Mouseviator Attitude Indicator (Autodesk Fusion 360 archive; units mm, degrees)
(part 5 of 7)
sketch "Sketch2"
  dimension "d14_1" = 20.32 (= "dip16_socket_length_1")
  dimension "d15_1" = 10.04 (= "dip16_socket_width_1")
extrude "Extrude2" sketch "Sketch2" blind 4.79 (= "dip16_socket_height_1 - dip16_socket_above_board_1") named "d16_1" taper 1 named "d17_1"
fillet "Fillet1" radius 0.5 named "d18_1"
sketch "Sketch3"
  dimension "d20_1" = 4
  dimension "d21_1" = 0.33
  dimension "d22_1" = 2.54
  dimension "d23_1" = 1.7
  dimension "d24_1" = 3.54 (= "0.1 in + 1 mm")
extrude "Extrude3" sketch "Sketch3" blind 1.5 named "d25_1"
extrude "Extrude4" sketch "Sketch3" blind 5.04 (= "dip16_socket_height_1") named "d27_1"
sketch "Sketch4"
  dimension "d29_1" = 9.04 (= "dip16_socket_width_1 - 1 mm")
  dimension "d30_1" = 1
  dimension "d31_1" = 5.04 (= "dip16_socket_height_1")
extrude "Extrude5" sketch "Sketch4" no distance stored
work_plane "WorkPlane1"
sketch "Sketch5"
  dimension "d33_1" = 5.04 (= "dip16_socket_height_1")
  dimension "d34_1" = 0.5
  dimension "d35_1" = 2.25
  dimension "d36_1" = 4.645 (= "( dip16_socket_width_1 - 0.75 mm ) / 2")
  dimension "d37_1" = 4.395 (= "( dip16_socket_width_1 - 1.25 mm ) / 2")
  dimension "d38_1" = 0.75 (= "dip16_socket_above_board_1 + 0.5 mm")
  dimension "d39_1" = 45
  dimension "d40_1" = 45
  dimension "d41_1" = 0.16 (= "dip16_socket_lead_thick_1")
  dimension "d42_1" = 0.25 (= "dip16_socket_above_board_1")
  dimension "d44_1" = 3
extrude "Extrude6" sketch "Sketch5" blind 1.25 (= "dip16_socket_lead_width_1") named "d45_1"
rectangular_pattern "R-Pattern1" countU 8 (= "dip16_num_leads_1 / 2") named "d50_1" uSpaceDistance -2.54 named "d52_1" vSpaceDistance 0 named "d53_1"
mirror "Mirror1"
work_plane "WorkPlane1" AlongDistance 8.89 (= "( ( dip16_num_leads_1 / 2 - 1 ) * dip16_socket_lead_spacing_1 ) / 2") named "d55_1"
sketch "Sketch1"
  dimension "d56_1" = 4.54 (= "dip16_socket_height_1 - 0.5 mm")
  dimension "d57_1" = 4.62 (= "dip16_socket_width_1 / 2 - 0.4 mm")
  dimension "d58_1" = 1.75
  dimension "d59_1" = 0.25
  dimension "d61_1" = 2.6667
  dimension "d62_1" = 0.76 (= "dip16_socket_above_board_1 + 0.51 mm")
  dimension "d63_1" = 0.5
  dimension "d64_1" = 0.67
  dimension "d65_1" = 97
  dimension "d66_1" = 1
  dimension "d67_1" = 0.5
  dimension "d68_1" = 0.16
  dimension "d71_1" = 0.16 (= "dip16_socket_lead_thick_1")
  dimension "d72_1" = 0.725
  dimension "d73_1" = 0.25
  dimension "d74_1" = 3.16 (= "dip16_socket_lead_length_1 - dip16_socket_height_1")
extrude "Extrude1" sketch "Sketch1" blind 0.625 (= "dip16_socket_lead_width_1 / 2") named "d69_1"
extrude "Extrude2" sketch "Sketch1" blind 0.31 (= "dip16_socket_lead_foot_width_1 / 2") named "d75_1"
sketch "Sketch2"
  dimension "d85_1" = 60
extrude "Extrude3" sketch "Sketch2" no distance stored
rectangular_pattern "R-Pattern1" countU 8 (= "dip16_num_leads_1 / 2") named "d77_1" uSpaceDistance -2.54 (= "-dip16_socket_lead_spacing_1") named "d79_1" vSpaceDistance 0 named "d80_1"
mirror "Mirror1"
sketch "Sketch1"
  circle C1 centre (10.16, 0) radius 0.625
  dimension "d82_1" diameter C1 = 1.25
  dimension "d83_1" distance = 10.16 (= "dip16_socket_length_1 / 2")
extrude "Extrude7" sketch "Sketch1" no distance stored
position "Position4"
work_plane "WorkPlane4" AlongDistance 2.5
sketch "Sketch3"
  dimension "d119" = 6
  dimension "d120" = 10
  dimension "d121" = 0.1
  dimension "d122" = 0.2
  dimension "d124" = 0.2
  dimension "d125" = 0.4
  dimension "d126" = 1.6
  dimension "d128" = 0.9
  dimension "d129" = 0.7
  dimension "d131" = 0.25
  dimension "d132" = 0.7
  dimension "d134" = 0.3
  dimension "d135" = 0.3
revolve "Revolve1" sketch "Sketch3" AlongAngle 360
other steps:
create_component "CreateComponent1"
create_component "CreateComponent4"
create_component "CreateComponent6"
create_component "CreateComponent7"
create_component "CreateComponent10"
create_component "CreateComponent1"
create_component "CreateComponent2"
create_component "CreateComponent11"
create_component "CreateComponent1"
create_component "CreateComponent1"
create_component "CreateComponent2"
create_component "CreateComponent3"
remove_instance "RemoveInstance1"
remove_instance "RemoveInstance2"
create_component "CreateComponent13"
create_component "CreateComponent1"
create_component "CreateComponent2"
create_component "CreateComponent3"
remove_instance "RemoveInstance1"
remove_instance "RemoveInstance2"
create_component "CreateComponent14"
create_component "CreateComponent1"
create_component "CreateComponent2"
create_component "CreateComponent15"

design "microswitch 10T85"
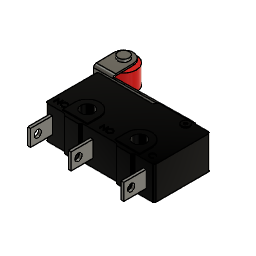
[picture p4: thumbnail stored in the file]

design "Bezel BOXY LED and Glass MS33638C" references "LED D5 - White-Clear"
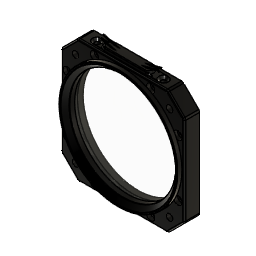
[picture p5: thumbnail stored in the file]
parameter "d52" = 0.15
canvas "Canvas4"
canvas "Canvas1"
canvas "Canvas5"
sketch "Instrument Sketch" plane through (0, 0, 0) normal (0, 1, 0) x axis (-1, 0, 0)
  line L1 (0, 0) -> (0, 39.6875)
  line L2 (-42.3978, 0) -> (0, 0)
  line L3 (-1.0967, 0) -> (0, 0)
  line L4 (-72.2485, 72.2485) -> (0, 0)
  line L5 (30, 41.2776) -> (0, 41.2776)
  line L6 (41.2776, 30) -> (30, 41.2776)
  line L7 (41.2776, 0) -> (41.2776, 30)
  line L8 (30, -41.2776) -> (0, -41.2776)
  line L9 (41.2776, -30) -> (30, -41.2776)
  line L10 (41.2776, 0) -> (41.2776, -30)
  line L11 (-30, 41.2776) -> (0, 41.2776)
  line L12 (-41.2776, 30) -> (-30, 41.2776)
  line L13 (-41.2776, 0) -> (-41.2776, 30)
  line L14 (-30, -41.2776) -> (0, -41.2776)
  line L15 (-41.2776, -30) -> (-30, -41.2776)
  line L16 (-41.2776, 0) -> (-41.2776, -30)
  circle C1 centre (0, 0) radius 39.6875
  circle C2 centre (31.4309, 31.4309) radius 2.159
  circle C3 centre (-31.4309, -31.4309) radius 2.159
  circle C4 centre (-31.4309, 31.4309) radius 2.159
  circle C5 centre (31.4309, -31.4309) radius 2.159
  circle C6 centre (0, 0) radius 35.5256
  point P1 (0, 0)
  point P2 (0, 0)
  point P11 (0, 0)
  point P13 (0, 0)
  point P14 (-1.0967, 0)
  point P12 (0, 0)
  point P15 (0, 0)
  point P4 (0, 39.6875)
  point P18 (0, 41.2776)
  point P19 (0, 41.2776)
  point P9 (0, 0)
  point P22 (41.2776, 0)
  point P10 (0, 0)
  point P23 (0, -41.2776)
  point P20 (30, 41.2776)
  point P24 (30, -41.2776)
  point P21 (41.2776, 30)
  point P25 (41.2776, -30)
  point P26 (41.2776, 0)
  point P27 (0, 41.2776)
  point P28 (-30, 41.2776)
  point P29 (-41.2776, 30)
  point P30 (-41.2776, 0)
  point P31 (0, -41.2776)
  point P32 (-30, -41.2776)
  point P33 (-41.2776, -30)
  point P34 (-41.2776, 0)
  coincident P1 P2
  equal C3 C4
  equal C3 C5
  equal C2 C5
  coincident P1 P11
  coincident P1 P13
  coincident L2 P14
  perpendicular L1 L3
  coincident P12 P15
  coincident C1 P4
  vertical L1
  coincident P18 P19
  perpendicular L1 L5
  vertical L7
  horizontal P9 P22
  vertical P10 P18
  coincident P2 P12
  coincident P2 P9
  vertical P12 P18
  symmetric L2 P19 P23
  symmetric L2 P20 P24
  symmetric L2 P21 P25
  symmetric L2 P22 P26
  symmetric L1 P19 P27
  symmetric L1 P20 P28
  symmetric L1 P21 P29
  symmetric L1 P22 P30
  symmetric L1 P23 P31
  symmetric L1 P24 P32
  symmetric L1 P25 P33
  symmetric L1 P26 P34
  dimension "d1" diameter C1 = 79.375 (= "3 1/8")
  dimension "d13" angle L1 L4 = 45 (= "Angular Dimension-2")
  dimension "d150" angle L5 L6 = 135 (= "Angular Dimension-3")
  dimension "d151" distance P19 P20 = 30
  dimension "d152" distance P21 P22 = 30
extrude "Extrude1" new body sketch "Instrument Sketch" profile of C1 C2 C3 C4 C5 C6 along a picked direction blind 10.25
extrude "Extrude2" sketch "Instrument Sketch" profile of C1 C6 blind 3
chamfer "Chamfer1" distance 3
canvas "Canvas2"
canvas "Canvas3"
move "Move1"
fillet "Fillet1" radius 0.5 0.25
sketch "Sketch2" plane through (0, 0, 0) normal (0, 1, 0) x axis (-1, 0, 0)
  line L1 (0, 32.0284) -> (0, 40.649)
  line L2 (-1.5, -39.15) -> (1.5, -39.15)
  line L3 (-1.5, -41.65) -> (-1.5, -39.15)
  line L4 (1.5, -41.65) -> (-1.5, -41.65)
  line L5 (1.5, -39.15) -> (1.5, -41.65)
  line L6 (-1.5, -41.65) -> (1.5, -39.15)
  line L7 (1.5, -41.65) -> (-1.5, -39.15)
  line L8 (30, -41.2776) -> (-30, -41.2776)
  line L9 (41.2776, -30) -> (30, -41.2776)
  line L10 (41.2776, 30) -> (41.2776, -30)
  line L11 (30, 41.2776) -> (41.2776, 30)
  line L12 (-30, 41.2776) -> (30, 41.2776)
  line L13 (-41.2776, 30) -> (-30, 41.2776)
  line L14 (-41.2776, -30) -> (-41.2776, 30)
  line L15 (-30, -41.2776) -> (-41.2776, -30)
  circle C1 centre (-31.4309, -31.4309) radius 2.159
  circle C2 centre (31.4309, 31.4309) radius 2.159
  circle C3 centre (31.4309, -31.4309) radius 2.159
  circle C4 centre (-31.4309, 31.4309) radius 2.159
  circle C5 centre (0, 0) radius 35.5256
  circle C6 centre (0, 0) radius 39.65
  point P1 (0, 0)
  point P7 (0, 0)
  point P9 (0, 32.0284)
  point P10 (0, 35.3825)
  point P11 (0.742, 39.6431)
  point P16 (0, -40.4)
  point P14 (-1.5, -41.65)
  point P15 (1.5, -41.65)
  point P13 (-1.5, -39.15)
  coincident P1 P7
  vertical L1
  vertical P7 P9
  coincident L1 P10
  coincident C6 P11
  horizontal L2
  perpendicular L2 L3
  parallel L2 L4
  parallel L3 L5
  coincident L6 P16
  coincident L7 P16
  vertical P1 P16
  dimension "d19" diameter C6 = 79.3
  dimension "d50" distance P14 P15 = 3
  dimension "d51" distance P13 P14 = 2.5
  dimension "d67" distance C6 L4 = 2
extrude "Extrude3" cut sketch "Sketch2" profile of C5 C6 L2 L3 L4 L5 to an object offset -6.5
sketch "Sketch1" plane through (0, -6.75, 0) normal (0, 1, 0) x axis (-1, 0, 0)
  line L1 (0, 40.6) -> (0.6381, 39.4948)
  line L2 (-0.6381, 39.4948) -> (0, 40.6)
  line L3 (1.5, -39.6216) -> (1.5, -41.2776)
  line L4 (-1.5, -41.2776) -> (-1.5, -39.6216)
  line L5 (1.5, -41.2776) -> (-1.5, -41.2776)
  circle C1 centre (0, 0) radius 35.5256
  circle C2 centre (0, 0) radius 39.55
  arc A1 centre (0, 0) radius 39.5 clockwise from (0.6381, 39.4948) to (-0.6381, 39.4948)
  arc A2 centre (0, 0) radius 39.65 clockwise from (-1.5, -39.6216) to (1.5, -39.6216)
  point P1 (0, 0)
  point P3 (0, 0)
  coincident P1 P3
extrude "Extrude1" new body sketch "Sketch1" profile of C1 C2 L1 L2 A1 L3 L4 along normal blind 3
sketch "Sketch1" plane through (0, -3.75, 0) normal (0, 1, 0) x axis (-1, 0, 0)
  line L1 (1.35, -38.7521) -> (1.35, -39.6216)
  line L2 (-1.35, -38.2133) -> (-1.35, -39.6216)
  line L3 (1.35, -41.2776) -> (1.35, -39.6216)
  line L4 (1.5, -41.4276) -> (-1.5, -41.4276)
  line L5 (-1.35, -39.6216) -> (-1.35, -41.2776)
  line L6 (1.5, -39.6216) -> (1.5, -41.2776)
  line L7 (-1.5, -41.2776) -> (-1.5, -39.6216)
  line L8 (1.5, -41.2776) -> (-1.5, -41.2776)
  circle C1 centre (0, 0) radius 39.65
  circle C2 centre (0, 0) radius 36.65
  circle C3 centre (0, 0) radius 39.5
  parallel L1 L3
  parallel L2 L5
  dimension "d25" diameter C1 = 79.3
  dimension "d29" = -3
  dimension "d68" = -0.15
extrude "Extrude1" new body sketch "Sketch1" profile of C1 C2 L8 C3 L5 L3 L1 L2 to an object bodies "Seal"
sketch "Panel Sketch" plane through (0, -10.25, 0) normal (0, -1, 0) x axis (1, 0, 0)
  line L1 (30, -41.2776) -> (-30, -41.2776)
  line L2 (41.2776, -30) -> (30, -41.2776)
  line L3 (41.2776, 30) -> (41.2776, -30)
  line L4 (30, 41.2776) -> (41.2776, 30)
  line L5 (-30, 41.2776) -> (30, 41.2776)
  line L6 (-41.2776, 30) -> (-30, 41.2776)
  line L7 (-41.2776, -30) -> (-41.2776, 30)
  line L8 (-30, -41.2776) -> (-41.2776, -30)
  circle C1 centre (31.4309, 31.4309) radius 2.159
  circle C2 centre (-31.4309, -31.4309) radius 2.159
  circle C3 centre (-31.4309, 31.4309) radius 2.159
  circle C4 centre (31.4309, -31.4309) radius 2.159
  circle C5 centre (0, 0) radius 39.6875
sketch "Clamping Holes" plane through (0, -10.25, 0) normal (0, -1, 0) x axis (1, 0, 0)
  line L1 (0, 17.2297) -> (0, 0)
  line L2 (-22.2137, 0) -> (0, 0)
  circle C1 centre (-36.96, 18.76) radius 1
  circle C2 centre (36.96, 18.76) radius 1
  circle C3 centre (-36.96, -18.76) radius 1
  circle C4 centre (36.96, -18.76) radius 1
  circle C5 centre (-18.76, 36.96) radius 1
  circle C6 centre (18.76, 36.96) radius 1
  circle C7 centre (18.76, -36.96) radius 1
  circle C8 centre (-18.76, -36.96) radius 1
  point P1 (0, 0)
  point P3 (0, 0)
  point P5 (0, 0)
  point P2 (-36.96, 18.76)
  point P10 (-18.76, 36.96)
  coincident P1 P3
  vertical L1
  coincident P1 P5
  perpendicular L1 L2
  symmetric C1 L1 C2
  symmetric C1 L2 C3
  symmetric L2 C2 C4
  symmetric L1 C5 C6
  symmetric L2 C5 C8
  symmetric L2 C6 C7
  dimension "d32" diameter C1 = 2
  dimension "d33" distance P1 P2 = 18.76 (= "( 37.52 / 2 ) * 1 mm")
  dimension "d34" distance P1 P2 = 36.96 (= "( 73.92 / 2 ) * 1 mm")
  dimension "d37" diameter C5 = 2 (= "d32")
  dimension "d38" distance P1 P10 = 36.96 (= "d34")
  dimension "d39" distance P1 P10 = 18.76 (= "d33")
hole "Hole1" HoleDepth 10.25 HoleDiameter 2.8 CBDepth 2.5 CBDiameter 5.5
component_from_bodies "Body->Comp"
sketch "Top Sketch" plane through (0, 0, 41.4655) normal (0, 0, 1) x axis (-1, 0, 0)
  line L1 (-22.19, 8) -> (22.19, 8)
  line L2 (22.19, 2) -> (-22.19, 2)
  line L3 (-22.19, 5) -> (22.19, 5)
  line L4 (22.19, 1.85) -> (-22.19, 1.85)
  line L5 (-22.19, 8.15) -> (22.19, 8.15)
  line L6 (-15.15, 1.85) -> (15.15, 1.85)
  line L7 (-15.15, 8.15) -> (-15.15, 1.85)
  line L8 (15.15, 8.15) -> (-15.15, 8.15)
  line L9 (15.15, 1.85) -> (15.15, 8.15)
  line L10 (-15.15, 8.15) -> (15.15, 1.85)
  line L11 (15.15, 8.15) -> (-15.15, 1.85)
  line L12 (-30, 0) -> (30, 0)
  line L13 (30, 0) -> (-30, 0)
  line L14 (30, 10.25) -> (30, 0)
  line L15 (-30, 10.25) -> (30, 10.25)
  line L16 (-30, 0) -> (-30, 10.25)
  arc A1 centre (-22.19, 5) radius 3 clockwise from (-22.19, 2) to (-22.19, 8)
  arc A2 centre (22.19, 5) radius 3 clockwise from (22.19, 8) to (22.19, 2)
  arc A3 centre (22.19, 5) radius 3.15 clockwise from (22.19, 8.15) to (22.19, 1.85)
  arc A4 centre (-22.19, 5) radius 3.15 clockwise from (-22.19, 1.85) to (-22.19, 8.15)
  point P8 (0, 5)
  point P1 (0, 0)
  point P15 (15.15, 1.85)
  point P19 (0, 5)
  point P7 (-22.19, 5)
  point P6 (22.19, 5)
  point P17 (-15.15, 8.15)
  point P18 (15.15, 8.15)
  tangent L1 A1
  tangent A1 L2
  parallel L1 L2
  tangent L2 A2
  tangent L1 A2
  horizontal L3
  midpoint L3 P8
  vertical P1 P8
  horizontal L6
  perpendicular L6 L7
  parallel L6 L8
  parallel L7 L9
  coincident L4 P15
  coincident L10 P19
  coincident L11 P19
  coincident P8 P19
  dimension "d54" diameter A1 = 6
  dimension "d56" distance P7 L12 = 5
  dimension "d57" distance P6 P7 = 44.38
  dimension "d60" = 0.15
  dimension "d70" distance P17 P18 = 30.3
extrude "Extrude2" cut sketch "Top Sketch" profile of L1 A1 L2 A2 L4 L5 A3 A4 against normal blind 1.7
extrude "Extrude2" cut sketch "Top Sketch" profile of L1 L2 L4 L5 L6 L7 L8 L9 to an object
work_plane "WorkPlane1"
sketch "LED Angle" plane through (0, -5, 41.4655) normal (0, -1, 0) x axis (1, 0, 0)
  line L1 (14.8802, -5) -> (-0.0147, -1.0089)
  line L2 (50, -10.3752) -> (0, -10.3752)
  line L3 (0, 22.6624) -> (0, -10.6292)
  line L4 (-14.8802, -5) -> (-0.0147, -1.0089)
  line L5 (-30, -0.1879) -> (30, -0.1879)
  point P1 (0, 0)
  point P2 (0, -10.6292)
  point P3 (14.8802, -5)
  point P8 (-14.8802, -5)
  horizontal L2
  vertical P1 P2
  perpendicular L2 L3
  symmetric P3 L3 P8
  dimension "d104" angle L1 L2 = 15 (= "Angular Dimension-2")
pipe "Pipe2" SectionSize 6.5 SectionThickness 1.375
component_insert "Component Insert"
joint "Assemble1" alignOffsetX 0 alignOffsetY 0 alignOffsetZ -3
copy_paste "CutPaste"
work_plane "WorkPlane1"
mirror_component "MirrorComponent1"
derived_instance "DerivedInstance1"
mirror "Mirror1" mirrorStitchTolerance 0.1
extrude "Extrude1" new body sketch "Top Sketch" profile of L1 A1 L2 A2 L7 L9 against normal blind 1.7 bodies "Top LED Holder"
sketch "Top Sketch" plane through (0, 0, 41.4655) normal (0, 0, 1) x axis (-1, 0, 0)
  line L1 (-22.19, 8) -> (22.19, 8)
  line L2 (22.19, 2) -> (-22.19, 2)
  line L3 (0, 8) -> (0, 2)
  line L4 (-12.5, 7.975) -> (12.5, 7.975)
  line L5 (12.5, 2.025) -> (-12.5, 2.025)
  line L6 (-12.5, 5) -> (12.5, 5)
  line L7 (-13.6, 8.9) -> (13.6, 8.9)
  line L8 (13.6, 1.1) -> (-13.6, 1.1)
  line L9 (-13.6, 5) -> (13.6, 5)
  arc A1 centre (22.19, 5) radius 3 clockwise from (22.19, 8) to (22.19, 2)
  arc A2 centre (-22.19, 5) radius 3 clockwise from (-22.19, 2) to (-22.19, 8)
  arc A3 centre (-12.5, 5) radius 2.975 clockwise from (-12.5, 2.025) to (-12.5, 7.975)
  arc A4 centre (12.5, 5) radius 2.975 clockwise from (12.5, 7.975) to (12.5, 2.025)
  arc A5 centre (-13.6, 5) radius 3.9 clockwise from (-13.6, 1.1) to (-13.6, 8.9)
  arc A6 centre (13.6, 5) radius 3.9 clockwise from (13.6, 8.9) to (13.6, 1.1)
  circle C1 centre (-15.475, 5) radius 2.5
  circle C2 centre (15.475, 5) radius 2.5
  circle C3 centre (16.5801, 5) radius 1.5
  point P8 (0, 2)
  point P9 (0, 8)
  point P16 (0, 5)
  point P22 (-13.6, 5)
  point P23 (0, 5)
  point P24 (-15.475, 5)
  point P25 (15.475, 5)
  point P26 (16.5801, 5)
  midpoint L2 P8
  midpoint L1 P9
  tangent L4 A3
  tangent A3 L5
  parallel L4 L5
  tangent L5 A4
  tangent L4 A4
  perpendicular L3 L6
  midpoint L3 P16
  midpoint L6 P16
  tangent L7 A5
  tangent A5 L8
  parallel L7 L8
  tangent L8 A6
  tangent L7 A6
  coincident L6 P22
  parallel L6 L9
  coincident P16 P23
  midpoint L9 P23
  midpoint A3 P24
  midpoint A4 P25
  horizontal P23 P26
  dimension "d115" distance L4 L5 = 5.95
  dimension "d116" = 30.95
  dimension "d117" distance L7 L8 = 7.8
  dimension "d118" = 35
  dimension "d123" diameter C2 = 5
  dimension "d124" diameter C1 = 5 (= "d123")
  dimension "d126" diameter C3 = 3
extrude "Extrude2" add sketch "Top Sketch" profile of L4 A3 L5 A4 C1 C2 C3 along normal blind 2
extrude "Extrude3" add sketch "Top Sketch" profile of L1 L2 L4 A3 L5 A4 L7 A5 L8 A6 C1 C2 along normal blind 1
chamfer "Chamfer1" distance 0.8
extrude "Extrude4" cut sketch "Top Sketch" profile of A4 A6 C2 C3 to an object
sketch "Bottom Sketch" plane through (0, 0, 39.7655) normal (0, 0, -1) x axis (1, 0, 0)
  line L1 (22.19, 2) -> (-22.19, 2)
  line L2 (-22.19, 8) -> (22.19, 8)
  line L3 (9, 2) -> (-9, 2)
  line L4 (-9, 8) -> (9, 8)
  line L5 (9, 5) -> (-9, 5)
  line L6 (-11.5981, 6.5) -> (-16.5801, 6.5)
  line L7 (-11.5981, 3.5) -> (-11.5981, 6.5)
  line L8 (-16.5801, 3.5) -> (-11.5981, 3.5)
  line L9 (-16.5801, 6.5) -> (-16.5801, 3.5)
  circle C1 centre (-16.5801, 5) radius 1.5
  arc A1 centre (-22.19, 5) radius 3 clockwise from (-22.19, 2) to (-22.19, 8)
  arc A2 centre (22.19, 5) radius 3 clockwise from (22.19, 8) to (22.19, 2)
  circle C2 centre (-16.5801, 5) radius 1
  arc A3 centre (9, 5) radius 3 clockwise from (9, 8) to (9, 2)
  arc A4 centre (-9, 5) radius 3 clockwise from (-9, 2) to (-9, 8)
  point P16 (0, 5)
  point P19 (-11.5981, 3.5)
  point P17 (-16.5801, 6.5)
  point P20 (-16.5801, 3.5)
  point P9 (-16.5801, 5)
  point P1 (0, 0)
  point P15 (9, 5)
  concentric C1 C2
  tangent L3 A3
  tangent A3 L4
  parallel L3 L4
  tangent L4 A4
  tangent L3 A4
  parallel L1 L5
  midpoint L5 P16
  horizontal L6
  vertical L7
  horizontal L8
  vertical L9
  coincident A4 P19
  coincident C1 P17
  coincident C1 P20
  vertical P9 P20
  vertical P1 P16
  horizontal P9 P16
  dimension "d129" diameter A3 = 6
  dimension "d130" distance P15 P16 = 9
extrude "Extrude5" cut sketch "Bottom Sketch" profile of C1 L1 L2 L3 A3 L4 A4 L6 L7 L8 against normal blind 1
extrude "Extrude6" cut sketch "Bottom Sketch" profile of L1 L2 L3 A3 L4 A4 L7 against normal blind 2.5
work_plane "WorkPlane1"
hole "Hole1" HoleDepth 7 HoleDiameter 3.2 CSDiameter 6.3
fillet "Fillet1" radius 2 1
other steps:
derived_base_feature "Derived Base Feature"
pipe "Pipe2" SectionSize 6.5 SectionThickness 1.375
mirror "Mirror1" mirrorStitchTolerance 0.1
base_feature "Base Feature" bodies "Standard Bezel"
extrude "Extrude1" cut sketch "Top Sketch" profile of L1 A1 L2 A2 L4 L5 A3 A4 against normal blind 1.7
pipe "Pipe2" SectionSize 6.5 SectionThickness 1.375
mirror "Mirror1" mirrorStitchTolerance 0.1
hole "Hole1" HoleDepth 7 HoleDiameter 3.2 CSDiameter 6.3
create_component "CreateComponent1"
create_component "CreateComponent2"
create_component "CreateComponent4"
remove_body "RemoveBody1"
extrude "Extrude2" cut sketch "Top Sketch" profile of L1 A1 L2 A2 L4 L5 A3 A4 against normal blind 1.7
joint_origin "JointOrigin1"
create_component "CreateComponent5"
remove_instance "RemoveInstance1"
create_component "CreateComponent1"
create_component "CreateComponent6"
named bodies: "Standard Bezel", "Seal", "Top LED Holder"

design "LED D5 - White-Clear"
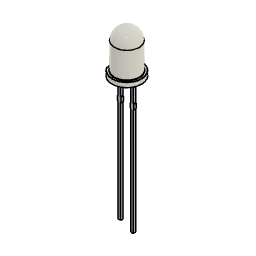
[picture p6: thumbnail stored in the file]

design "G1000/Steam C172 Panel Sketch"
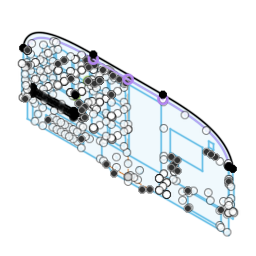
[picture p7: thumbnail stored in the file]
parameter "Instrumentknobdimension" = 6.35 (= "0.25")
parameter "d3" = 4.318 (= "0.17")
parameter "d241" = 37
parameter "d250" = 10
parameter "d252" = 10
parameter "d294" = 6.35 (= "0.25")
parameter "d300" = 2
parameter "d302" = 1
parameter "d146" = 4.318 (= "0.17")
parameter "d314" = 342.9 (= "13.5")
parameter "d247" = 6.35 (= "Instrumentknobdimension")
parameter "d248" = 6.35 (= "Instrumentknobdimension")
parameter "d329" = 8.001 (= "0.315")
parameter "d386" = 7.62 (= "0.3")
parameter "d104" = 270 (= "d101")
base_feature "Base Feature"
copy_paste "CutPaste"
canvas "Canvas1"
canvas "Canvas3"
canvas "Canvas6"
canvas "Canvas7"
canvas "Canvas9" sketch "Analog Master"
canvas "Canvas10" sketch "Analog Master"
sketch "Analog Master" plane through (0, 0, 0) normal (0, 1, 0) x axis (1, 0, 0)
  line L1 (-172.9706, -420) -> (0, -420)
  curve K1 (69.9424, 20) -> (107.8843, 0)
  curve K2 (104.8876, -0.1472) -> (110.8811, 0.1472)
  curve K3 (65.1162, 20) -> (74.7686, 20)
  line L2 (-351.7202, -281.627) -> (-346.953, -286.548)
  line L3 (-230, -95.25) -> (-230, -204.9762)
  line L4 (-81.0384, -309.4306) -> (-77.9862, -312.4827)
  line L5 (-132.2958, -407.803) -> (-200.571, -407.803)
  line L6 (-200.571, -387.483) -> (-132.2958, -387.483)
  line L7 (-141.0632, -344.0205) -> (-183.9378, -301.1803)
  line L8 (154.9321, -66.0556) -> (171.4865, -66.0556)
  line L9 (183.7415, -29.4869) -> (190.7415, -29.4869)
  line L10 (0, 20) -> (-69.9424, 20)
  line L11 (-125.1584, -397.643) -> (-207.7084, -397.643)
  line L12 (-350.0664, -224.1613) -> (-345.1455, -219.3941)
  line L13 (-215.012, -148.0279) -> (-244.9883, -193.745)
  line L14 (176.0865, -23.2779) -> (183.7415, -23.2779)
  line L15 (171.4865, -69.6959) -> (171.4865, -66.0556)
  line L16 (-387.2335, -62.0569) -> (-407.5535, -31.1959)
  line L17 (183.7415, -63.4869) -> (183.7415, -69.6959)
  line L18 (154.9321, -27.0556) -> (176.0865, -27.0556)
  line L19 (-194.9837, -314.302) -> (-199.7509, -309.3811)
  line L20 (183.7415, -23.2779) -> (183.7415, -29.4869)
  line L21 (-475.361, -115.57) -> (-270.51, -115.57)
  line L22 (154.9321, -27.0556) -> (154.9321, -66.0556)
  line L23 (-72.0304, -387.5197) -> (-14.8804, -407.8397)
  line L24 (-97.5147, -420) -> (-97.5147, -204.6151)
  curve K4 (-172.9706, -420) -> (-500, -294.703)
  curve K5 (-500, -302.074) -> (-500, -287.3319)
  curve K6 (-81.7028, -420) -> (-264.2385, -420)
  line L25 (-500, 0) -> (-500, -294.703)
  line L26 (-77.9862, -312.4827) -> (-82.4764, -316.9729)
  line L27 (-362.4853, -405.0994) -> (-362.4853, -205.3372)
  line L28 (-68.068, -387.5197) -> (-18.8428, -387.5197)
  line L29 (183.7415, -69.6959) -> (171.4865, -69.6959)
  line L30 (-11.7054, -397.6797) -> (-75.2054, -397.6797)
  line L31 (0, 20) -> (69.9424, 20)
  line L32 (-97.5147, -204.6151) -> (-362.4853, -205.3372)
  line L33 (430.0639, -313.9668) -> (394.0639, -291.2168)
  line L34 (303.15, -12.7) -> (455.55, -12.7)
  line L35 (230, -95.25) -> (230, -170.8864)
  line L36 (226.825, -136.7885) -> (226.825, -151.8364)
  line L37 (461.9, -19.05) -> (461.9, -82.55)
  line L38 (190.7415, -63.4869) -> (183.7415, -63.4869)
  line L39 (-215.0138, -193.7463) -> (-244.9862, -148.0266)
  line L40 (-350.9585, -313.9207) -> (-347.9064, -316.9729)
  line L41 (-221.945, -62.2703) -> (-242.265, -62.2703)
  line L42 (-129.4939, -406.6425) -> (-203.3728, -388.6436)
  line L43 (-343.4162, -312.4827) -> (-346.4684, -309.4306)
  line L44 (-262.7234, -316.3565) -> (-257.8025, -311.5893)
  line L45 (176.0865, -27.0556) -> (176.0865, -23.2779)
  line L46 (-82.4764, -316.9729) -> (-85.5285, -313.9207)
  line L47 (-407.5535, -62.0569) -> (-387.2335, -31.1959)
  line L48 (-284.4986, -279.1718) -> (-289.4196, -283.939)
  line L49 (-141.0006, -273.7447) -> (-141.0006, -252.9947)
  line L50 (-221.945, -62.2703) -> (-242.265, -31.4093)
  line L51 (-85.5285, -313.9207) -> (-81.0384, -309.4306)
  line L52 (190.7415, -63.4869) -> (190.7415, -29.4869)
  line L53 (-128.3334, -391.4454) -> (-128.3334, -403.8406)
  line L54 (-347.9064, -316.9729) -> (-343.4162, -312.4827)
  line L55 (-242.265, -31.4093) -> (-221.945, -31.4093)
  line L56 (-215.0118, -148.0279) -> (-244.9882, -193.745)
  line L57 (-346.4684, -309.4306) -> (-350.9585, -313.9207)
  line L58 (-242.265, -62.2703) -> (-242.265, -31.4093)
  line L59 (-259.8999, -309.4241) -> (-264.8209, -314.1913)
  line L60 (-242.265, -62.2703) -> (-221.945, -31.4093)
  line L61 (-263.5469, -222.4237) -> (-260.3145, -225.656)
  line L62 (-201.9161, -311.4786) -> (-197.1489, -316.3995)
  line L63 (-221.945, -31.4093) -> (-221.945, -62.2703)
  line L64 (-226.825, -151.8364) -> (-226.825, -136.7885)
  line L65 (-270.51, -153.67) -> (-475.361, -153.67)
  line L66 (-178.3239, -233.3974) -> (-181.0614, -230.4108)
  line L67 (-130.43, -95.25) -> (-130.43, 0)
  line L68 (-215.014, -193.7463) -> (-244.9863, -148.0266)
  line L69 (-255.8244, -221.1659) -> (-259.0567, -217.9336)
  line L70 (-197.0382, -372.2859) -> (-201.9591, -377.0531)
  line L71 (-204.5334, -403.8406) -> (-204.5334, -391.4454)
  line L72 (-260.3145, -225.656) -> (-255.8244, -221.1659)
  line L73 (-317.2825, -274.1666) -> (-317.2825, -253.4166)
  line L74 (-203.9172, -221.166) -> (-200.6849, -217.9337)
  line L75 (-407.5535, -31.1959) -> (-387.2335, -31.1959)
  line L76 (-387.2335, -62.0569) -> (-407.5535, -62.0569)
  line L77 (-195.9894, -373.3685) -> (-200.9104, -378.1357)
  line L78 (-196.1948, -222.4239) -> (-199.4271, -225.6562)
  line L79 (-344.7878, -284.4505) -> (-349.555, -279.5295)
  line L80 (-233.175, -136.7885) -> (-233.175, -151.8364)
  line L81 (-159.0062, -214.0642) -> (-161.995, -211.3291)
  line L82 (-229.8709, -274.1095) -> (-229.8709, -253.3595)
  line L83 (-230, -136.7885) -> (-230, -151.8364)
  line L84 (-287.3221, -286.1042) -> (-282.4011, -281.337)
  line L85 (-282.8449, -221.7061) -> (-287.6121, -216.7852)
  line L86 (-289.7773, -218.8827) -> (-285.0101, -223.8036)
  line L87 (-199.4271, -225.6562) -> (-203.9172, -221.166)
  line L88 (-347.243, -217.2289) -> (-352.1639, -221.9961)
  line L89 (-259.0567, -217.9336) -> (-263.5469, -222.4237)
  line L90 (-473.33, 0) -> (-473.33, -95.25)
  line L91 (-455.6291, -41.2995) -> (-456.3216, -44.2584)
  line L92 (-159.0062, -306.7742) -> (-161.995, -304.0391)
  line L93 (-199.8616, -379.2183) -> (-194.9407, -374.4511)
  line L94 (-264.7779, -374.3404) -> (-260.0107, -379.2613)
  line L95 (-457.2048, -40.9307) -> (-455.6291, -41.2995)
  line L96 (-257.8455, -377.1638) -> (-262.6127, -372.2429)
  line L97 (-283.4499, -280.2544) -> (-288.3709, -285.0216)
  line L98 (-130.43, -95.25) -> (-500, -95.25)
  line L99 (430.0639, -291.2168) -> (430.0639, -313.9668)
  line L100 (424.3755, -328.0702) -> (424.3755, -353.8202)
  line L101 (424.3755, -353.8202) -> (400.8755, -353.8202)
  line L102 (400.8755, -353.8202) -> (400.8755, -328.0702)
  line L103 (394.0639, -291.2168) -> (430.0639, -291.2168)
  line L104 (394.0639, -313.9668) -> (430.0639, -291.2168)
  line L105 (500, 0) -> (500, -294.703)
  line L106 (244.6336, -193.9737) -> (215.3665, -147.7992)
  line L107 (455.55, -88.9) -> (303.15, -88.9)
  line L108 (245.3372, -148.2606) -> (214.6628, -193.5123)
  line L109 (296.8, -82.55) -> (296.8, -19.05)
  line L110 (233.175, -151.8364) -> (233.175, -136.7885)
  line L111 (434.0639, -302.5918) -> (390.0639, -302.5918)
  line L112 (394.0639, -313.9668) -> (394.0639, -291.2168)
  line L113 (-140.9488, -366.4547) -> (-140.9571, -345.7047)
  line L114 (-107.8843, 0) -> (-500, 0)
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  point P434 (-500, -95.25)
  point P450 (-65.1162, 20)
  point P445 (-97.5147, -420)
  point P454 (-230, -204.9762)
  point P438 (-230, -95.25)
  point P463 (-473.33, 0)
  point P453 (-130.43, 0)
  point P521 (-244.9862, -148.0266)
  point P522 (-244.9862, -148.0266)
  point P513 (-215.0138, -193.7463)
  point P520 (-215.0138, -193.7463)
  point P515 (-244.9882, -193.745)
  point P519 (-244.9882, -193.745)
  point P510 (-215.0118, -148.0279)
  point P518 (-215.0118, -148.0279)
  point P506 (-230, -170.8864)
  point P540 (-230, -172.0094)
  point P538 (215.3665, -147.7992)
  point P546 (215.3665, -147.7992)
  point P536 (244.6336, -193.9737)
  point P542 (244.6336, -193.9737)
  point P524 (214.6628, -193.5123)
  point P545 (214.6628, -193.5123)
  point P525 (245.3372, -148.2606)
  point P534 (245.3372, -148.2606)
  point P541 (230, -170.8864)
  point P466 (230, -170.8864)
  point P523 (-244.9863, -148.0266)
  point P528 (-244.9863, -148.0266)
  point P527 (-215.014, -193.7463)
  point P530 (-215.014, -193.7463)
  point P526 (-244.9883, -193.745)
  point P533 (-244.9883, -193.745)
  point P535 (-215.012, -148.0279)
  point P539 (-215.012, -148.0279)
  point P531 (-230.0002, -170.8864)
  point P548 (412.0639, -302.5918)
  point P9 (390.0639, -302.5918)
  point P11 (390.0639, -302.5918)
  point P5 (434.0639, -302.5918)
  point P6 (434.0639, -302.5918)
  point P84 (-397.3935, -46.6264)
  point P38 (-232.105, -46.8398)
  point P430 (-317.4627, -342.9264)
  point P468 (-317.4627, -342.9264)
  point P242 (-166.4334, -397.643)
  point P239 (-125.1584, -397.643)
  point P246 (-125.1584, -397.643)
  point P224 (-207.7084, -397.643)
  point P228 (-207.7084, -397.643)
  point P233 (-69.13, -387.5197)
  point P237 (-43.4554, -397.6797)
  point P219 (-75.2054, -397.6797)
  point P249 (-75.2054, -397.6797)
  point P250 (-11.7054, -397.6797)
  point P251 (-11.7054, -397.6797)
  point P40 (-500, -240.3186)
  point P397 (-500, -219.7071)
  point P196 (-500, -230.1092)
  point P305 (-230, -136.7885)
  point P316 (230, -151.8364)
  point P357 (-500, -230.1092)
  point P12 (500, -230.1092)
  point P355 (500, -230.1092)
  point P97 (-83.2834, -311.6757)
  point P100 (-83.2834, -311.6757)
  point P107 (-83.2834, -311.6757)
  point P406 (-83.2834, -311.6757)
  point P458 (-172.9706, -420)
  point P96 (-81.7028, -420)
  point P427 (-500, -294.703)
  point P99 (-500, -287.3319)
  point P462 (-362.4853, -405.0994)
  point P325 (-167.035, -318.0695)
  point P337 (-141.0632, -344.0205)
  point P343 (-141.0632, -344.0205)
  point P58 (-141.0632, -344.0205)
  point P342 (-141.0632, -344.0205)
  point P47 (-141.0632, -344.0205)
  point P319 (-141.0632, -344.0205)
  point P338 (-141.0632, -344.0205)
  point P130 (-182.3338, -317.1904)
  point P333 (-167.9264, -302.7714)
  point P140 (-178.3239, -326.1074)
  point P339 (-159.0062, -306.7742)
  point P133 (-177.9375, -328.5066)
  point P351 (-156.6067, -307.1586)
  point P141 (-181.0614, -323.1208)
  point P341 (-161.995, -304.0391)
  point P340 (-182.3338, -317.1904)
  point P157 (-348.7134, -311.6757)
  point P469 (-348.7134, -311.6757)
  point P155 (296.8, -88.9)
  point P212 (296.8, -88.9)
  point P156 (461.9, -88.9)
  point P158 (296.8, -12.7)
  point P232 (-14.8804, -387.5197)
  point P244 (-72.0304, -387.5197)
  point P114 (154.9321, -27.0556)
  point P216 (-114.6925, -393.6524)
  point P370 (-114.6925, -400.5012)
  point P365 (-261.3018, -220.1786)
  point P581 (-261.3018, -220.1786)
  point P582 (-266.4009, -227.4609)
  point P583 (-266.4009, -227.4609)
  point P404 (-270.51, -147.32)
  point P508 (-270.51, -147.32)
  point P401 (-475.234, -147.32)
  point P580 (-475.234, -147.32)
  point P516 (-413.8295, -147.32)
  point P421 (-464.947, -134.62)
  point P586 (-481.711, -134.62)
  point P277 (-200.8335, -310.4298)
  point P592 (-200.8335, -310.4298)
  point P276 (-196.0663, -315.3508)
  point P593 (-196.0663, -315.3508)
  point P537 (394.0639, -313.9668)
  point P544 (430.0639, -313.9668)
  point P543 (394.0639, -291.2168)
  point P63 (400.8755, -353.8202)
  point P65 (424.3755, -353.8202)
  point P66 (400.8755, -328.0702)
  point P26 (-221.945, -62.2703)
  point P44 (-221.945, -31.4093)
  point P19 (-242.265, -31.4093)
  point P347 (-157.3424, -304.07)
  point P326 (-166.4909, -310.5651)
  point P231 (-14.8804, -407.8397)
  point P240 (-72.0304, -407.8397)
  point P210 (-58.04, -11.75)
  point P189 (-58.04, -56.2)
  point P32 (-463.0064, -85.1913)
  point P512 (491.999, -85.217)
  point P403 (-475.234, -123.19)
  point P517 (-270.51, -121.92)
  point P1 (0, 0)
  point P587 (-264.16, -134.62)
  point P588 (209.55, -311.15)
  point P589 (369.57, -311.15)
  point P473 (0, 0)
  point P591 (209.55, -209.55)
  perpendicular L25 L114
  perpendicular L10 L25
  coincident P434 L25
  perpendicular L25 L98
  coincident P450 L10
  coincident P445 L1
  perpendicular L1 L24
  perpendicular L67 L98
  midpoint P454 L32
  coincident P438 L98
  coincident P463 L114
  perpendicular L90 L114
  coincident P453 L114
  coincident P521 P522
  coincident P513 P520
  coincident P515 P519
  coincident P510 P518
  midpoint L39 L56
  midpoint P506 L56
  coincident P540 L3
  coincident P538 P546
  coincident P536 P542
  coincident P524 P545
  coincident P525 P534
  midpoint L106 L108
  midpoint P541 L108
  coincident P466 P541
  coincident P523 P528
  coincident P527 P530
  coincident P526 P533
  coincident P535 P539
  midpoint L13 L68
  midpoint P531 L13
  perpendicular L103 L112
  parallel L99 L112
  coincident P548 L104
  coincident P548 L33
  coincident P9 P11
  coincident P5 P6
  midpoint P548 L111
  parallel L75 L76
  coincident P84 L47
  coincident P84 L16
  perpendicular L55 L58
  parallel L41 L55
  parallel L58 L63
  coincident P38 L60
  coincident P38 L50
  coincident P430 P468
  midpoint P242 L42
  midpoint P242 L11
  coincident P239 P246
  coincident P224 P228
  coincident P233 L28
  coincident P237 L23
  midpoint P237 L30
  coincident P219 P249
  coincident P250 P251
  parallel L70 L93
  coincident P40 L25
  coincident P397 L25
  coincident P196 L25
  parallel L64 L80
  coincident P305 L3
  parallel L3 L83
  parallel L36 L110
  coincident P316 L35
  equal L41 L76
  coincident P196 P357
  coincident P12 P355
  perpendicular L46 L51
  parallel L26 L51
  parallel L4 L46
  coincident P97 P100
  midpoint P107 L51
  coincident P107 P406
  midpoint P458 K6
  coincident P96 L1
  midpoint P427 K5
  coincident P99 L25
  coincident P462 K4
  coincident P325 L7
  coincident P337 P343
  coincident P58 P342
  coincident P47 P342
  coincident P337 P342
  coincident P319 P342
  coincident P319 P338
  symmetric P130 P333 L7
  symmetric P140 P339 L7
  symmetric P133 P351 L7
  symmetric P141 P341 L7
  coincident P130 P340
  perpendicular L43 L57
  parallel L54 L57
  parallel L40 L43
  midpoint P157 L57
  coincident P157 P469
  coincident P155 P212
  coincident P155 L107
  coincident P155 L109
  coincident P156 L107
  coincident P156 L37
  coincident P158 L109
  coincident P158 L34
  parallel L48 L84
  perpendicular L69 L89
  parallel L72 L89
  parallel L61 L69
  parallel L74 L78
  coincident P232 L28
  coincident P244 L28
  perpendicular L9 L52
  perpendicular L9 L20
  perpendicular L14 L52
  perpendicular L14 L45
  coincident P114 L22
  perpendicular L18 L22
  perpendicular L38 L52
  perpendicular L8 L15
  vertical P216 P370
  coincident P365 P581
  coincident P582 P583
  horizontal L65
  horizontal L21
  coincident P404 P508
  coincident P401 P580
  horizontal P516 P580
  horizontal P421 P586
  coincident P277 P592
  coincident P276 P593
  dimension "d10" distance L10 L114 = 20
  dimension "d12" distance L98 L114 = 95.25 (= "3.75")
  dimension "d15" distance L1 L114 = 420
  dimension "d40" distance = 160.02 (= "6.3")
  dimension "d85" diameter = 12.065 (= "0.475")
  dimension "d90" diameter = 4.318 (= "0.170")
  dimension "d101" distance L3 L25 = 270
  dimension "d102" distance L35 L105 = 270
  dimension "d113" diameter = 4.318 (= "0.17")
  dimension "d114" angle L39 L56 = 66.5 (= "Angular Dimension-2")
  dimension "d115" distance P520 P521 = 54.6684 (= "2.152301")
  dimension "d116" distance P518 P519 = 54.6684 (= "2.152301")
  dimension "d117" diameter = 4.318 (= "0.17")
  dimension "d118" angle L106 L108 = 66.5 (= "Angular Dimension-3")
  dimension "d119" distance P536 P538 = 54.6684 (= "2.152301")
  dimension "d120" distance P534 P545 = 54.6684 (= "2.152301")
  dimension "d121" diameter = 4.318 (= "0.17")
  dimension "d122" angle L13 L68 = 66.5 (= "Angular Dimension-4")
  dimension "d123" distance P528 P530 = 54.6684 (= "2.152301")
  dimension "d124" distance P533 P539 = 54.6684 (= "2.152301")
  dimension "d125" distance P537 P544 = 36
  dimension "d126" distance P537 P543 = 22.75
  dimension "d127" diameter = 4.318 (= "0.17")
  dimension "d128" diameter = 4.318 (= "0.17")
  dimension "d130" distance P5 P11 = 44
  dimension "d131" distance P63 P65 = 23.5
  dimension "d132" distance P63 P66 = 25.75
  dimension "d141" diameter = 4.318 (= "0.17")
  dimension "d786" diameter = 4.318 (= "0.17")
  dimension "d151" diameter = 4.318 (= "0.17")
  dimension "d152" diameter = 4.318 (= "0.17")
  dimension "d153" diameter = 4.318 (= "0.17")
  dimension "d154" diameter = 4.318 (= "0.17")
  dimension "d155" diameter = 4.318 (= "0.17")
  dimension "d156" diameter = 4.318 (= "0.17")
  dimension "d157" diameter = 4.318 (= "0.17")
  dimension "d158" diameter = 4.318 (= "0.17")
  dimension "d159" diameter = 4.318 (= "0.17")
  dimension "d160" radius = 3.9624 (= "0.156")
  dimension "d161" diameter = 3.175 (= "0.125")
  dimension "d162" diameter = 4.318 (= "0.17")
  dimension "d163" diameter = 11.811 (= "0.465")
  dimension "d164" diameter = 11.811 (= "0.465")
  dimension "d165" diameter = 4.318 (= "0.17")
  dimension "d166" diameter = 4.318 (= "0.17")
  dimension "d169" diameter = 6.35 (= "0.25")
  dimension "d179" radius = 2.54 (= "0.1")
  dimension "d180" diameter = 3.81 (= "0.15")
  dimension "d181" diameter = 3.81 (= "0.15")
  dimension "d187" diameter = 38.1 (= "1.5")
  dimension "d189" distance L64 L80 = 6.35 (= "0.25")
  dimension "d190" distance L36 L110 = 6.35 (= "0.25")
  dimension "d191" distance P26 P44 = 30.861 (= "1.215")
  dimension "d192" distance P19 P44 = 20.32 (= "0.8")
  dimension "d249" diameter = 6.35 (= "Instrumentknobdimension")
  dimension "d269" angle L7 L113 = 135 (= "Angular Dimension-5")
  dimension "d270" radius = 49.2252 (= "1.938")
  dimension "d271" radius = 7.9248 (= "0.312")
  dimension "d272" radius = 3.175 (= "0.125")
  dimension "d275" angle P339 P347 P351 = 45 (= "Angular Dimension-6")
  dimension "d276" angle P326 P333 P341 = 45 (= "Angular Dimension-7")
  dimension "d277" distance P341 L7 = 13.4874 (= "( 1.062 / 2 ) * 1")
  dimension "d282" diameter = 6.35 (= "Instrumentknobdimension")
  dimension "d286" distance P155 P156 = 165.1 (= "6.5")
  dimension "d287" distance P155 P158 = 76.2 (= "3")
  dimension "d288" radius = 6.35 (= "0.25")
  dimension "d289" radius = 6.35 (= "0.25")
  dimension "d290" distance = 12.7 (= "0.5")
  dimension "d291" distance L37 L105 = 38.1 (= "1.5")
  dimension "d829" diameter = 6.35 (= "0.25")
  dimension "d295" diameter = 6.35 (= "d294")
  dimension "d296" diameter = 3
  dimension "d297" distance P219 P251 = 63.5 (= "2.5")
  dimension "d298" distance P231 P240 = 57.15 (= "2.25")
  dimension "d299" distance = 20.32 (= "0.8")
  dimension "d301" radius = 3.9624 (= "0.156")
  dimension "d303" distance P228 P239 = 82.55 (= "3.25")
  dimension "d304" distance L53 L71 = 76.2 (= "3")
  dimension "d305" distance L5 L6 = 20.32 (= "0.8")
  dimension "d306" diameter = 19.05 (= "0.75")
  dimension "d307" diameter = 13.97 (= "0.55")
  dimension "d308" diameter = 8
  dimension "d309" distance P210 L10 = 31.75 (= "1.25")
  dimension "d310" distance P189 L10 = 76.2 (= "3")
  dimension "d311" distance P189 L67 = 72.39 (= "2.85")
  dimension "d313" distance L25 L90 = 26.67 (= "1.05")
  dimension "d846" distance P463 L67 = 342.9 (= "13.5")
  dimension "d327" diameter = 5.08 (= "0.2")
  dimension "d328" diameter = 2.54 (= "0.1")
  dimension "d331" distance P32 L98 = 10.0587 (= "0.396011")
  dimension "d332" distance P512 L105 = 8.001 (= "0.315")
  dimension "d387" distance P403 L21 = 7.62 (= "0.3")
  dimension "d388" distance = 6.477 (= "0.255")
  dimension "d389" distance = 6.35 (= "0.25")
  dimension "d390" radius = 6.35 (= "0.25")
  dimension "d907" distance P581 P582 = 8.89 (= "0.35")
  dimension "d908" angle = 10 (= "Angular Dimension-8")
  dimension "d909" diameter = 3.175 (= "0.125")
  dimension "d910" diameter = 3.175 (= "d909")
  dimension "d911" diameter = 3.175 (= "d909")
  dimension "d912" diameter = 3.175 (= "0.125")
  dimension "d913" diameter = 3.175 (= "d909")
  dimension "d914" distance L21 L65 = 38.1 (= "1.5")
  dimension "d915" distance P517 L21 = 6.35 (= "0.25")
  dimension "d917" distance L65 P580 = 6.35 (= "0.25")
  dimension "d918" distance P516 L65 = 6.35 (= "0.25")
  dimension "d919" distance P508 L65 = 6.35 (= "0.25")
  dimension "d920" distance P508 L65 = 6.35 (= "( d919 + d915 ) / 2")
  dimension "d921" distance = 6.477 (= "0.255")
  dimension "d925" distance = 16.764 (= "0.66")
  dimension "d926" distance = 16.764 (= "0.66")
  dimension "d927" distance = 67.8815 (= "2.6725")
  dimension "d929" distance = 67.8815 (= "2.6725")
  dimension "d930" distance = 67.8815 (= "( d927 + d929 ) / 2")
  dimension "d933" distance = 264.16 (= "10.4")
  dimension "d935" diameter = 4.318 (= "d90")
  dimension "d936" distance P1 P587 = 134.62 (= "5.3")
  dimension "d937" distance P588 P589 = 160.02 (= "6.3")
  dimension "d940" distance P473 P591 = 209.55 (= "8.25")
  dimension "d941" distance = 101.6 (= "4")
  dimension "d942" distance P473 P591 = 209.55 (= "8.25")
  dimension "d943" diameter = 80.01 (= "3.15")
  dimension "d944" diameter = 80.01 (= "3.15")
  dimension "d945" diameter = 80.01 (= "3.15")
  dimension "d946" radius = 40.005 (= "( 3.15 / 2 ) * 1")
  dimension "d947" diameter = 80.01 (= "d943")
  dimension "d948" diameter = 80.01 (= "d943")
  dimension "d712" R-Pattern1-uDistance = 176.53 (= "6.95")
  dimension "d713" R-Pattern1-vDistance = 91.44 (= "3.60")
  dimension "d720" R-Pattern3-uDistance = -63.5 (= "-2.50")
  dimension "d721" R-Pattern3-vDistance = 143.51 (= "5.65")
  dimension "d724" R-Pattern4-uDistance = 20.447 (= "0.805")
  dimension "d725" R-Pattern4-vDistance = 0 (= "0.00")
  dimension "d728" R-Pattern5-uDistance = 204.724 (= "8.06")
  dimension "d729" R-Pattern5-vDistance = -25.4 (= "-1")
  dimension "d732" R-Pattern6-uDistance = 81.788 (= "3.22")
  dimension "d733" R-Pattern6-vDistance = 25.4 (= "1.0")
  dimension "d736" R-Pattern7-uDistance = 121.92 (= "4.80")
  dimension "d737" R-Pattern7-vDistance = 40.64 (= "1.60")
  dimension "d740" R-Pattern8-uDistance = 182.626 (= "7.19")
  dimension "d741" R-Pattern8-vDistance = 0 (= "0.00")
  dimension "d744" R-Pattern9-uDistance = 39.116 (= "1.54")
  dimension "d745" R-Pattern9-vDistance = 77.216 (= "3.04")
  dimension "d748" R-Pattern10-uDistance = 93.726 (= "3.69")
  dimension "d749" R-Pattern10-vDistance = 77.216 (= "3.04")
  dimension "d751" value = 360 (= "C-Pattern1-Angle")
  dimension "d754" R-Pattern11-uDistance = 0 (= "0.00")
  dimension "d755" R-Pattern11-vDistance = 92.71 (= "3.65")
  dimension "d757" value = 360 (= "C-Pattern2-Angle")
  dimension "d859" R-Pattern11-uDistance = -88.9 (= "-3.5")
  dimension "d860" R-Pattern11-vDistance = 190.5 (= "7.5")
canvas "Canvas1" sketch "Analog Master"
canvas "Canvas2"
sketch "Panel Outside" plane through (0, 0, 0) normal (0, 0, 1) x axis (1, 0, 0)
  curve K1 (516.8494, 103.4791) -> (185.2741, 251.4075)
  line L1 (521.9136, 47.9852) -> (516.8494, 103.4791)
  line L2 (521.9136, 47.9852) -> (520.3159, 24.7393)
  line L3 (520.3159, 24.7393) -> (513.9582, 24.7393)
  line L4 (513.9582, 24.7393) -> (513.9582, 19.9074)
  line L5 (513.9582, 19.9074) -> (526.6736, 19.9074)
  line L6 (526.6736, 19.9074) -> (526.6736, -98.7273)
  line L7 (526.6736, -98.7273) -> (522.3504, -98.7273)
  line L8 (522.3504, -98.7273) -> (522.3504, -124.2853)
  line L9 (522.3504, -124.2853) -> (500.0011, -124.2853)
  curve K2 (-0.5752, 246.6606) -> (363.2394, 234.5529)
  line L10 (-520.7148, -120.9367) -> (-500.0055, -120.9372)
  line L11 (-520.7141, -93.2641) -> (-520.7148, -120.9367)
  line L12 (-525.7316, -93.264) -> (-520.7141, -93.2641)
  line L13 (-525.7287, 23.416) -> (-525.7316, -93.264)
  line L14 (-511.005, 23.4156) -> (-525.7287, 23.416)
  line L15 (-511.0048, 29.7274) -> (-511.005, 23.4156)
  line L16 (-518.3668, 29.7276) -> (-511.0048, 29.7274)
  line L17 (-518.3668, 52.5456) -> (-518.3668, 29.7276)
  line L18 (-518.3668, 52.5456) -> (-516.8536, 103.4992)
  curve K3 (-364.3897, 234.5529) -> (-516.8536, 103.4992)
  curve K4 (-0.5752, 246.6606) -> (-364.3897, 234.5529)
  line L19 (367.4149, 233.8901) -> (363.2394, 234.5529)
  circle C1 centre (-512.4973, -18.6283) radius 10.795
  circle C2 centre (-508.9635, -64.567) radius 15.875
  circle C3 centre (509.464, -68.4031) radius 15.875
  point P22 (363.2394, 234.5529)
  point P49 (363.2394, 234.5529)
  point P50 (367.4149, 233.8901)
  coincident P22 P49
  coincident K1 P50
  dimension "d182" diameter C2 = 31.75 (= "1.25")
  dimension "d183" diameter C1 = 21.59 (= "0.85")
  dimension "d184" diameter C3 = 31.75 (= "1.25")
